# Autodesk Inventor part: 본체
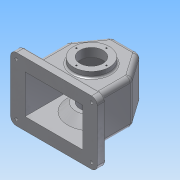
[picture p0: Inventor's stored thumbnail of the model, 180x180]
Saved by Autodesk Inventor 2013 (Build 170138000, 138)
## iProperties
Created: 2016-12
Part Number: 본체
Material: 알루미늄 6061
Document SubType Name: Modeling
Designer: Administrator
Density: 2.71 g/cm^3
Mass: 1083.53 g
Surface Area: 1169.44 cm^2
Volume: 399.825 cm^3
Author: Administrator
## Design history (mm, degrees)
sketch "스케치1"
  geometry: L1 (0, 0)-(0, 80); L2 (0, 80)-(31.509, 125); L3 (0, 0)-(110, 0); L4 (110, 0)-(110, 80); L5 (110, 80)-(78.491, 125); L6 (78.491, 125)-(31.509, 125)
  constraints: 12 end point, 2 perpendicular, 1 equal length, 1 vertical
  dimensions: "d0" = 110 distance of L1.start L3.end; "d1" = 80 distance of L1.start L1.end; "d2" = 35 deg angle of L1 L2; "d3" = 80 distance of L3.end L4.end; "d4" = 125 distance between parallel lines of L3 L6; "d5" = 35 deg angle of L4 L5
extrude "돌출1" new body sketch "스케치1" distance "d6" = 77; taper "d7" = 0 deg
fillet "모깎기1" dims "d8" = 10
feature "쉘1" dims "d9" = 5
node "작업 평면1"
sketch "스케치2"
  geometry: L1 (-117.868, -72)-(-79.715, -72) reference; L2 (-76.847, -72)-(-79.715, -72) reference; L3 (-76.847, -5)-(-76.847, -72) reference; L4 (-76.847, -72)-(0, -72) reference; L5 (0, -5)-(0, -72) reference; L6 (0, -5)-(-76.847, -5) reference; L7 (-120.736, -77)-(-82.583, -77) reference; L8 (-76.847, -77)-(-82.583, -77) reference; L9 (-76.847, -77)-(0, -77) reference; L10 (-106, -72)-(-92, -58); L11 (-92, -58)-(-85, -58); L12 (-85, -58)-(-85, -72); L13 (-65, -72)-(-65, -5)
  constraints: 8 end point, 4 point on line, 2 perpendicular, 1 parallel
  dimensions: "d10" = 65 distance between parallel lines of L5 L13; "d11" = 54 diameter of L10.end L13; "d12" = 40 diameter of L12 L13; "d13" = 45 deg angle of L11 L10; "d14" = 14 distance of L11.end L12.end
revolve "회전1" sketch "스케치2" stored, may be unused: angle "d15" = 90 deg
sketch "스케치3"
  geometry: L1 (-110, 76.847)-(-110, 0) reference; L2 (-110, 0)-(0, 0) reference; C1 r 20 at (-55, 65); C2 r 37.5 at (-55, 65)
  constraints: 2 centre point, 1 coincident
  dimensions: "d16" = 65 distance from line of C1.centre L2; "d17" = 40 diameter of C1; "d18" = 75 diameter of C2; "d19" = 55 distance from line of C1.centre L1
extrude "돌출2" join sketch "스케치3" distance "d20" = 5; taper "d21" = 0 deg
sketch "스케치4"
  geometry: C1 r 20 at (0, 0) reference; C2 r 20 at (0, 0); 1 further point
  constraints: 1 centre point, 1 coincident
  dimensions: "d22" = 40 diameter of C2
extrude "돌출3" cut sketch "스케치4" stored distance "d24" = 5; taper "d25" = 0 deg
sketch "스케치5"
  geometry: C1 r 20 at (55, 65) reference; C2 r 31 at (55, 65); C3 r 20 at (55, 65)
  constraints: 2 centre point, 2 coincident, 1 concentric
  dimensions: "d26" = 62 diameter of C2
extrude "돌출4" join sketch "스케치5" distance "d28" = 10; taper "d29" = 0 deg
node "작업 평면2"
sketch "스케치8"
  geometry: L1 (5, 5)-(5, 72) reference; L2 (110, 0)-(0, 0) reference; L3 (110, 0)-(110, 77) reference; L4 (0, 77)-(110, 77) reference; L5 (0, 0)-(0, 77) reference; L6 (-20, 93.5)-(130, 93.5); L7 (130, 93.5)-(130, -16.5); L8 (130, -16.5)-(-20, -16.5); L9 (-20, -16.5)-(-20, 93.5); 2 further points
  constraints: 8 end point, 2 midpoint, 2 parallel, 1 horizontal, 1 perpendicular
  dimensions: "d40" = 110 distance of L8.end L6.start; "d42" = 150 distance of L6.start L6.end; "d43" = 55 distance from line of point (5, 38.5) L6; "d44" = 75 horizontal distance of L6.start point (55, 77)
extrude "돌출6" join sketch "스케치8" distance "d45" = 15; taper "d46" = 0 deg
fillet "모깎기2" dims "d47" = 8
fillet "모깎기3" dims "d48" = 3
fillet "모깎기4" dims "d49" = 10
fillet "모깎기5" dims "d50" = 3
sketch "스케치9"
  geometry: C1 r 2.5 at (-10, 6.5); C2 r 2.5 at (120, 6.5); C3 r 2.5 at (120, -83.5); C4 r 2.5 at (-10, -83.5); A1 r 7 centre (120, 6.5) between (127, 6.5) and (120, 13.5) reference; A2 r 7 centre (-10, 6.5) between (-10, 13.5) and (-17, 6.5) reference; A3 r 7 centre (-10, -83.5) between (-17, -83.5) and (-10, -90.5) reference; A4 r 7 centre (120, -83.5) between (120, -90.5) and (127, -83.5) reference; 1 further point
  constraints: 4 centre point, 4 coincident
  dimensions: "d51" = 5 diameter of C1; "d53" = 5 diameter of C2; "d54" = 5 diameter of C3; "d55" = 5 diameter of C4
extrude "돌출7" cut sketch "스케치9" stored distance "d56" = 15; taper "d57" = 0 deg
sketch "스케치10"
  geometry: C1 r 2.5 at (120, -83.5) reference; C2 r 2.5 at (-10, 6.5) reference; C3 r 2.5 at (120, 6.5) reference; C4 r 2.5 at (-10, -83.5) reference; C5 r 6 at (-10, 6.5); C6 r 6 at (120, 6.5); C7 r 6 at (120, -83.5); C8 r 6 at (-10, -83.5); A1 r 7 centre (120, 6.5) between (127, 6.5) and (120, 13.5) reference; A2 r 7 centre (-10, 6.5) between (-10, 13.5) and (-17, 6.5) reference; A3 r 7 centre (-10, -83.5) between (-17, -83.5) and (-10, -90.5) reference; A4 r 7 centre (120, -83.5) between (120, -90.5) and (127, -83.5) reference; 1 further point
  constraints: 4 centre point, 4 coincident
  dimensions: "d58" = 12 diameter of C5; "d60" = 12 diameter of C6; "d61" = 12 diameter of C7; "d62" = 12 diameter of C8
extrude "돌출8" cut sketch "스케치10" distance "d63" = 5; taper "d64" = 0 deg
sketch "스케치11" dims "d65" = 52
  geometry: C1 r 20 at (0, 0) reference; C2 r 31 at (0, 0) reference; 6 further points
  constraints: 2 vertical alignment, 1 coincident, 7 other
  dimensions: "d69" = 360 deg dimension on point (0, 0) point (0, 26) (derived)
hole "구멍1" sketch "스케치11" at (0, 26), (-26, 0), (0, -26), (26, 0) diameter "d71" = 2.459; stored, may be unused: countersink angle "d75" = 90 deg, drill point angle "d77" = 118 deg; dims "d72" = 6, "d73" = 4, "d74" = 2, "d76" = 8
node "작업 평면3"
node "작업 평면4"
node "작업 평면5"
sketch "스케치12" dims "d78" = 58
  geometry: C1 r 20 at (0, 0) reference; C2 r 37.5 at (0, 0) reference; 6 further points
  constraints: 2 vertical alignment, 1 coincident, 7 other
  dimensions: "d82" = 360 deg dimension on point (0, 0) point (0, 29) (derived)
hole "구멍2" sketch "스케치12" at (0, 29), (-29, 0), (0, -29), (29, 0) diameter "d84" = 2.459; stored, may be unused: countersink angle "d88" = 90 deg, drill point angle "d90" = 118 deg; dims "d85" = 6, "d86" = 4, "d87" = 2, "d89" = 8
sketch "스케치13"
  geometry: L1 (-0.044, -31.847)-(61.044, -31.847); L2 (30.5, -38.846)-(30.5, -24.848); L3 (-8, 0)-(-8, -58.847) reference; L4 (-14.5, -76.847)-(75.5, -76.847) reference; L5 (6.122, -28.706)-(55.897, -28.706); L6 (55.897, -28.706)-(55.897, -35.91); L7 (55.897, -35.91)-(6.122, -35.91); L8 (6.122, -35.91)-(6.122, -28.706); 1 further point
  constraints: 4 end point, 2 other
  dimensions: "d91" = 38.5 distance from line of L2.end L3; "d92" = 45 distance from line of L4 L1.end
feature "엠보싱1" sketch "스케치13" dims "d0" = 110, "d1" = 80, "d2" = 35 deg, "d3" = 80, "d4" = 125, "d5" = 35 deg, "d69" = 360 deg (derived), "d93" = 0.5, "d94" = 0
node "솔리드1"
node "투영된 루프1"
other parameters: "d33" = 65
